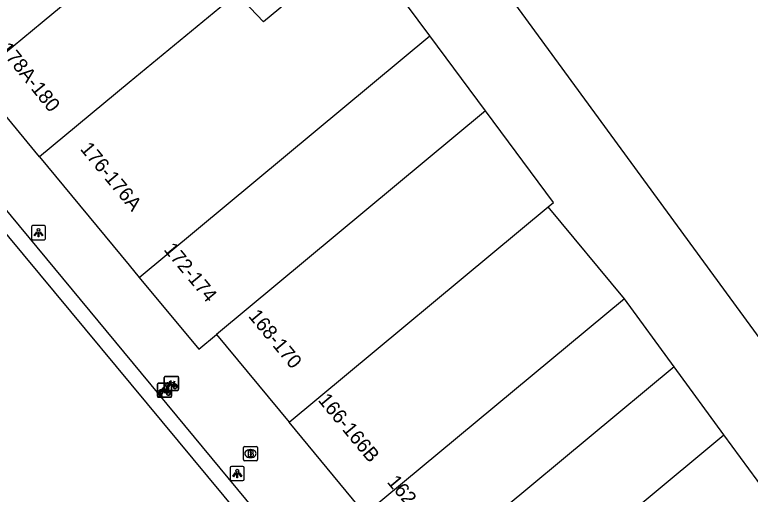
# Model space of a CAD drawing. Extents: x 160861 to 161308, y 384024 to 384878.
# Drawn here: x 160991.9 to 161043.8, y 384529.6 to 384563.5 of the extents above; entities that cross this region are included whole.
import ezdxf

# ---------------------------------------------------------------- set-up
doc = ezdxf.new("R2010")
doc.units = 0
for name, color, linetype in [('IMGEO_Brandkraan', 7, 'Continuous'), ('IMGEO_Fietsenrek', 7, 'Continuous'), ('IMGEO_Fietspad_gesloten', 7, 'Continuous'), ('IMGEO_Fietspad_open', 7, 'Continuous'), ('IMGEO_Lichtpunt', 7, 'Continuous'), ('IMGEO_Pand', 7, 'Continuous'), ('IMGEO_Pand_nummerreeks', 7, 'Continuous')]:
    doc.layers.add(name, color=color, linetype=linetype)

msp = doc.modelspace()

# ---------------------------------------------------------------- linework, layer by layer
at = {"layer": 'IMGEO_Brandkraan'}
for p, q in [((161008.062, 384532.06), (161008.062, 384532.912)), ((161008.137, 384532.986), (161008.989, 384532.986)), ((161009.063, 384532.912), (161009.063, 384532.06)), ((161008.55, 384532.766), (161008.575, 384532.766)), ((161008.989, 384531.986), (161008.137, 384531.986)), ((161008.573, 384532.206), (161008.548, 384532.206))]:
    msp.add_line(p, q, dxfattribs=at)
for points in [[(161008.062, 384532.06), (161008.062, 384532.912)], [(161008.137, 384532.986), (161008.989, 384532.986)], [(161009.063, 384532.912), (161009.063, 384532.06)], [(161008.41, 384532.686), (161008.41, 384532.286), (161008.623, 384532.286)], [(161008.641, 384532.686), (161008.41, 384532.686)], [(161008.589, 384532.605), (161008.535, 384532.605), (161008.535, 384532.529)], [(161008.535, 384532.529), (161008.588, 384532.529)], [(161008.597, 384532.453), (161008.535, 384532.453), (161008.535, 384532.372)], [(161008.535, 384532.372), (161008.597, 384532.372)], [(161008.989, 384531.986), (161008.137, 384531.986)]]:
    msp.add_lwpolyline(points, dxfattribs=at)
for centre, radius, start, end in [((161008.139, 384532.91), 0.0765, 91.552, 178.448), ((161008.139, 384532.91), 0.0765, 91.552, 178.448), ((161008.987, 384532.91), 0.0765, 1.552, 88.448), ((161008.987, 384532.91), 0.0765, 1.552, 88.448), ((161008.59, 384532.567), 0.0379, 267.8285, 90.9355), ((161008.598, 384532.412), 0.0404, 269.8759, 90.5077), ((161008.645, 384532.541), 0.145, 59.4692, 91.5367), ((161008.67, 384532.588), 0.0922, 285.5137, 58.1501), ((161008.675, 384532.396), 0.105, 301.3115, 78.989), ((161008.139, 384532.062), 0.0765, 181.552, 268.448), ((161008.139, 384532.062), 0.0765, 181.552, 268.448), ((161008.629, 384532.537), 0.251, 268.6676, 293.5347), ((161008.987, 384532.062), 0.0765, 271.552, 358.448), ((161008.987, 384532.062), 0.0765, 271.552, 358.448)]:
    msp.add_arc(centre, radius, start, end, dxfattribs=at)
for centre, major_axis, ratio, start_param, end_param in [((161008.549, 384532.486), (-0.387, 0.002), 0.722429, 4.712389, 7.853982), ((161008.574, 384532.486), (-0.39, 0.002), 0.717154, 1.570796, 4.712389)]:
    msp.add_ellipse(centre, major_axis=major_axis, ratio=ratio, start_param=start_param, end_param=end_param, dxfattribs=at)
at = {"layer": 'IMGEO_Fietsenrek'}
for p, q in [((161002.483, 384537.015), (161002.483, 384537.856)), ((161002.483, 384537.856), (161002.483, 384537.015)), ((161002.558, 384537.94), (161003.399, 384537.94)), ((161003.399, 384537.94), (161002.558, 384537.94)), ((161003.483, 384537.865), (161003.483, 384537.024)), ((161003.483, 384537.024), (161003.483, 384537.865)), ((161002.002, 384536.535), (161002.002, 384537.376)), ((161002.002, 384537.376), (161002.002, 384536.535)), ((161002.077, 384537.46), (161002.918, 384537.46)), ((161002.918, 384537.46), (161002.077, 384537.46)), ((161002.61, 384537.024), (161002.649, 384537.184)), ((161002.644, 384537.024), (161002.61, 384537.024)), ((161002.679, 384537.172), (161002.644, 384537.024)), ((161002.689, 384537.009), (161002.725, 384536.914)), ((161002.721, 384537.196), (161002.72, 384537.2)), ((161002.762, 384537.024), (161002.728, 384537.166)), ((161002.752, 384537.207), (161002.753, 384537.2)), ((161002.76, 384537.17), (161002.795, 384537.024)), ((161002.795, 384537.024), (161002.762, 384537.024)), ((161003.002, 384537.385), (161003.002, 384536.544)), ((161003.002, 384536.544), (161003.002, 384537.385)), ((161003.17, 384537.489), (161003.206, 384537.394)), ((161002.129, 384536.544), (161002.168, 384536.704)), ((161002.163, 384536.544), (161002.129, 384536.544)), ((161002.198, 384536.692), (161002.163, 384536.544)), ((161002.24, 384536.716), (161002.239, 384536.72)), ((161002.281, 384536.544), (161002.247, 384536.686)), ((161002.271, 384536.727), (161002.272, 384536.72)), ((161002.279, 384536.69), (161002.314, 384536.544)), ((161002.314, 384536.544), (161002.281, 384536.544)), ((161003.408, 384536.94), (161002.567, 384536.94)), ((161002.567, 384536.94), (161003.408, 384536.94)), ((161002.927, 384536.46), (161002.086, 384536.46)), ((161002.086, 384536.46), (161002.927, 384536.46))]:
    msp.add_line(p, q, dxfattribs=at)
for points in [[(161002.796, 384537.466), (161002.891, 384537.63), (161002.977, 384537.616), (161002.979, 384537.607), (161002.923, 384537.596), (161002.896, 384537.551), (161003.152, 384537.51)], [(161003.139, 384537.485), (161002.882, 384537.526), (161002.865, 384537.497), (161003.032, 384537.277), (161003.139, 384537.485)], [(161003.152, 384537.51), (161003.177, 384537.559), (161003.171, 384537.563), (161003.148, 384537.567), (161003.136, 384537.574), (161003.135, 384537.577), (161003.137, 384537.582), (161003.232, 384537.567), (161003.234, 384537.557), (161003.224, 384537.544), (161003.212, 384537.538), (161003.198, 384537.544), (161003.17, 384537.489)], [(161002.315, 384536.986), (161002.41, 384537.15), (161002.496, 384537.136), (161002.498, 384537.127), (161002.442, 384537.116), (161002.415, 384537.071), (161002.671, 384537.03)], [(161002.658, 384537.005), (161002.401, 384537.046), (161002.384, 384537.017), (161002.551, 384536.797), (161002.658, 384537.005)], [(161002.671, 384537.03), (161002.696, 384537.079), (161002.69, 384537.083), (161002.667, 384537.087), (161002.655, 384537.094), (161002.654, 384537.097), (161002.656, 384537.102), (161002.751, 384537.087), (161002.753, 384537.077), (161002.743, 384537.064), (161002.731, 384537.058), (161002.717, 384537.064), (161002.689, 384537.009)], [(161002.817, 384537.414), (161002.765, 384537.324), (161002.725, 384537.299), (161002.726, 384537.346), (161002.781, 384537.44)], [(161003.092, 384537.222), (161003.042, 384537.222), (161002.851, 384537.473), (161002.832, 384537.441)], [(161003.187, 384537.387), (161003.157, 384537.464), (161003.048, 384537.246), (161003.091, 384537.246)], [(161003.121, 384537.246), (161003.241, 384537.245), (161003.197, 384537.359)], [(161003.217, 384537.366), (161003.272, 384537.221), (161003.122, 384537.221)], [(161002.336, 384536.934), (161002.284, 384536.844), (161002.244, 384536.819), (161002.245, 384536.866), (161002.3, 384536.96)], [(161002.611, 384536.742), (161002.561, 384536.742), (161002.37, 384536.993), (161002.351, 384536.961)], [(161002.706, 384536.907), (161002.676, 384536.984), (161002.567, 384536.766), (161002.61, 384536.766)], [(161002.64, 384536.766), (161002.76, 384536.765), (161002.716, 384536.879)], [(161002.736, 384536.886), (161002.791, 384536.741), (161002.641, 384536.741)]]:
    msp.add_lwpolyline(points, dxfattribs=at)
for centre, radius, start, end in [((161002.561, 384537.862), 0.0779, 92.4484, 184.2845), ((161002.561, 384537.862), 0.0779, 92.4484, 184.2845), ((161003.405, 384537.862), 0.0779, 2.4484, 94.2845), ((161003.405, 384537.862), 0.0779, 2.4484, 94.2845), ((161002.08, 384537.382), 0.0779, 92.4484, 184.2845), ((161002.08, 384537.382), 0.0779, 92.4484, 184.2845), ((161002.242, 384536.845), 0.159, 62.6766, 242.1369), ((161002.561, 384537.018), 0.0779, 182.4484, 274.2845), ((161002.561, 384537.018), 0.0779, 182.4484, 274.2845), ((161002.723, 384537.325), 0.159, 62.6766, 242.1369), ((161002.723, 384537.325), 0.129, 63.3192, 238.903), ((161002.703, 384537.196), 0.0499, 12.8025, 158.6934), ((161002.723, 384537.325), 0.159, 253.9967, 271.7867), ((161002.703, 384537.196), 0.0174, 12.8025, 163.4502), ((161002.723, 384537.325), 0.129, 253.415, 269.0204), ((161002.723, 384537.325), 0.129, 283.6043, 43.4302), ((161002.723, 384537.325), 0.159, 283.5766, 46.6042), ((161002.924, 384537.382), 0.0779, 2.4484, 94.2845), ((161002.924, 384537.382), 0.0779, 2.4484, 94.2845), ((161003.25, 384537.241), 0.159, 113.3408, 178.3217), ((161003.25, 384537.241), 0.159, 187.0065, 105.7708), ((161003.25, 384537.241), 0.129, 113.923, 177.9556), ((161003.25, 384537.241), 0.129, 188.6715, 104.5883), ((161003.405, 384537.018), 0.0779, 272.4484, 4.2845), ((161003.405, 384537.018), 0.0779, 272.4484, 4.2845), ((161002.08, 384536.538), 0.0779, 182.4484, 274.2845), ((161002.08, 384536.538), 0.0779, 182.4484, 274.2845), ((161002.242, 384536.845), 0.129, 63.3192, 238.903), ((161002.222, 384536.716), 0.0499, 12.8025, 158.6934), ((161002.242, 384536.845), 0.159, 253.9967, 271.7867), ((161002.222, 384536.716), 0.0174, 12.8025, 163.4502), ((161002.242, 384536.845), 0.129, 253.415, 269.0204), ((161002.242, 384536.845), 0.129, 283.6043, 43.4302), ((161002.242, 384536.845), 0.159, 283.5766, 46.6042), ((161002.769, 384536.761), 0.159, 113.3408, 178.3217), ((161002.769, 384536.761), 0.159, 187.0065, 105.7708), ((161002.769, 384536.761), 0.129, 113.923, 177.9556), ((161002.769, 384536.761), 0.129, 188.6715, 104.5883), ((161002.924, 384536.538), 0.0779, 272.4484, 4.2845), ((161002.924, 384536.538), 0.0779, 272.4484, 4.2845)]:
    msp.add_arc(centre, radius, start, end, dxfattribs=at)
at = {"layer": 'IMGEO_Fietspad_gesloten'}
msp.add_lwpolyline([(161017.521, 384516.451), (160978.487, 384563.462)], dxfattribs=at)
at = {"layer": 'IMGEO_Fietspad_open'}
msp.add_lwpolyline([(161018.1, 384517.358), (160990.437, 384550.764), (160979.348, 384564.156)], dxfattribs=at)
at = {"layer": 'IMGEO_Lichtpunt'}
for p, q in [((160993.11, 384548.486), (160993.11, 384547.679)), ((160993.11, 384548.486), (160993.11, 384547.679)), ((160994.012, 384548.581), (160993.204, 384548.581)), ((160994.012, 384548.581), (160993.204, 384548.581)), ((160994.106, 384547.679), (160994.106, 384548.486)), ((160994.106, 384547.679), (160994.106, 384548.486)), ((160993.204, 384547.585), (160994.012, 384547.585)), ((160993.204, 384547.585), (160994.012, 384547.585)), ((161007.133, 384531.481), (161007.133, 384530.674)), ((161007.133, 384531.481), (161007.133, 384530.674)), ((161008.035, 384531.576), (161007.227, 384531.576)), ((161008.035, 384531.576), (161007.227, 384531.576)), ((161008.129, 384530.674), (161008.129, 384531.481)), ((161008.129, 384530.674), (161008.129, 384531.481)), ((161007.227, 384530.58), (161008.035, 384530.58)), ((161007.227, 384530.58), (161008.035, 384530.58))]:
    msp.add_line(p, q, dxfattribs=at)
for points in [[(160993.484, 384548.15), (160993.523, 384548.122), (160993.335, 384547.86), (160993.297, 384547.887), (160993.484, 384548.15)], [(160993.586, 384548.102), (160993.633, 384548.102), (160993.633, 384547.78), (160993.586, 384547.78), (160993.586, 384548.102)], [(160993.696, 384548.122), (160993.734, 384548.149), (160993.921, 384547.887), (160993.882, 384547.859), (160993.696, 384548.122)], [(161007.507, 384531.145), (161007.546, 384531.117), (161007.358, 384530.855), (161007.32, 384530.882), (161007.507, 384531.145)], [(161007.609, 384531.097), (161007.656, 384531.097), (161007.656, 384530.775), (161007.609, 384530.775), (161007.609, 384531.097)], [(161007.719, 384531.117), (161007.757, 384531.144), (161007.944, 384530.882), (161007.905, 384530.854), (161007.719, 384531.117)]]:
    msp.add_lwpolyline(points, dxfattribs=at)
for centre in [(160993.609, 384548.284), (161007.632, 384531.279)]:
    msp.add_circle(centre, 0.0994, dxfattribs=at)
for centre, start, end in [((160993.204, 384548.486), 90, 180), ((160993.204, 384548.486), 90, 180), ((160994.012, 384548.486), 0, 90), ((160994.012, 384548.486), 0, 90), ((160993.204, 384547.679), 180, 270), ((160993.204, 384547.679), 180, 270), ((160994.012, 384547.679), 270, 0), ((160994.012, 384547.679), 270, 360), ((161007.227, 384531.481), 90, 180), ((161007.227, 384531.481), 90, 180), ((161008.035, 384531.481), 0, 90), ((161008.035, 384531.481), 0, 90), ((161007.227, 384530.674), 180, 270), ((161007.227, 384530.674), 180, 270), ((161008.035, 384530.674), 270, 0), ((161008.035, 384530.674), 270, 360)]:
    msp.add_arc(centre, 0.0946, start, end, dxfattribs=at)
at = {"layer": 'IMGEO_Pand'}
for points in [[(160989.204, 384558.838), (160989.07, 384558.987), (161000, 384568.043), (161004.057, 384571.396)], [(161021.221, 384561.973), (161016.273, 384568.639)], [(161015.582, 384568.028), (161009.471, 384562.969), (161007.598, 384564.971), (161000, 384558.677), (160993.672, 384553.434)], [(161024.428, 384568.037), (161050.778, 384531.991)], [(161000.723, 384544.923), (161021.221, 384561.973)], [(161025.146, 384556.687), (161021.221, 384561.973)], [(160993.672, 384553.434), (160989.204, 384558.838)], [(161025.146, 384556.687), (161006.157, 384540.892)], [(161029.569, 384549.908), (161029.946, 384550.221), (161025.146, 384556.687)], [(160993.672, 384553.434), (161000, 384545.796), (161000.723, 384544.923)], [(161011.287, 384534.701), (161029.569, 384549.908)], [(161034.956, 384543.407), (161029.569, 384549.908)], [(161000.723, 384544.923), (161004.916, 384539.863), (161006.157, 384540.892)], [(161034.956, 384543.407), (161016.665, 384528.211)], [(161038.456, 384538.613), (161034.956, 384543.407)], [(161006.157, 384540.892), (161011.287, 384534.701)], [(161038.456, 384538.613), (161020.454, 384523.638)], [(161041.965, 384533.808), (161038.456, 384538.613)], [(161016.665, 384528.211), (161011.287, 384534.701)], [(161024.243, 384519.066), (161041.965, 384533.808)], [(161045.474, 384529.002), (161041.965, 384533.808)]]:
    msp.add_lwpolyline(points, dxfattribs=at)

# ---------------------------------------------------------------- texts
at = {"layer": 'IMGEO_Pand_nummerreeks'}
for s, rotation, p in [('178A-180', 308.8147, (160990.799, 384561.024)), ('176-176A', 309.74, (160996.502, 384553.974)), ('172-174', 309.4725, (161002.4, 384546.873)), ('168-170', 309.6459, (161008.369, 384542.172)), ('166-166B', 309.6472, (161013.283, 384536.242)), ('162-164', 309.9869, (161018.158, 384530.457))]:
    msp.add_text(s, height=1, rotation=rotation, dxfattribs=at).set_placement(p)

doc.saveas('drawing.dxf')
